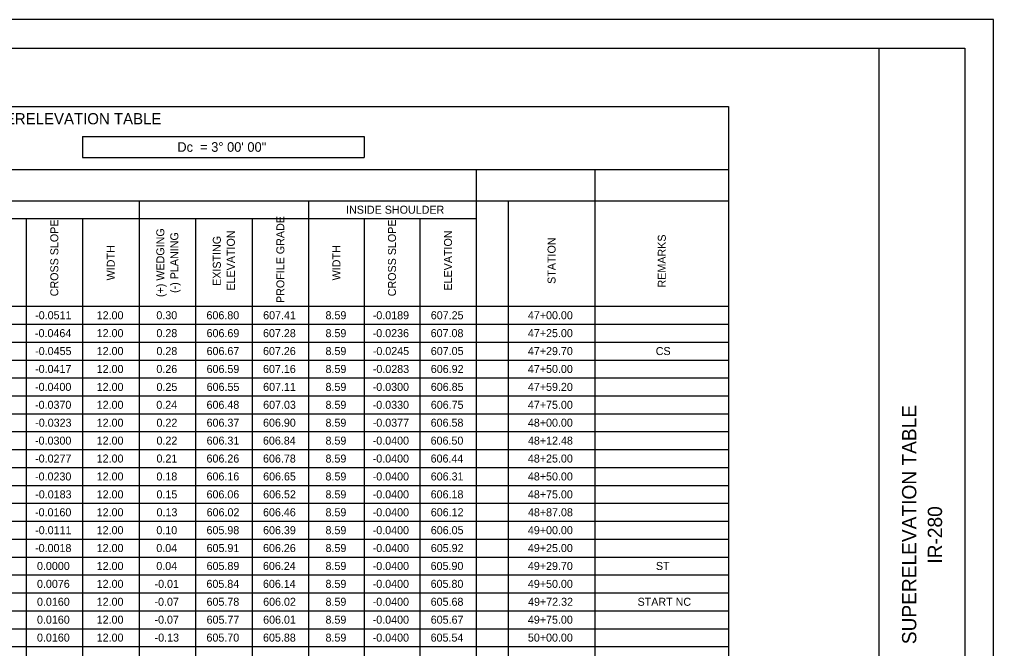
# Model space of a CAD drawing. Extents: x 0 to 34, y 0 to 22.
# Drawn here: x 16.97 to 34, y 11.01 to 22 of the extents above; entities that cross this region are included whole.
import ezdxf

# ---------------------------------------------------------------- set-up
doc = ezdxf.new("R2010")
doc.units = 0
for name, color, linetype in [('Default', 7, 'Continuous'), ('SH_Border', 7, 'Continuous'), ('SH_Cut_Line', 7, 'Continuous'), ('SH_Data', 7, 'Continuous')]:
    doc.layers.add(name, color=color, linetype=linetype)

msp = doc.modelspace()

# ---------------------------------------------------------------- linework, layer by layer
at = {"layer": 'Default'}
for p, q in [((4.135, 20.48), (29.368, 20.48)), ((29.368, 20.48), (29.368, 1.522)), ((18.069, 19.953), (22.994, 19.953)), ((18.069, 19.953), (18.069, 19.591)), ((22.994, 19.953), (22.994, 19.591)), ((18.069, 19.591), (22.994, 19.591)), ((4.135, 19.376), (29.368, 19.376)), ((24.954, 19.376), (24.954, 1.522)), ((27.029, 19.376), (27.029, 1.522)), ((4.135, 18.833), (29.368, 18.833)), ((19.057, 18.833), (19.057, 1.522)), ((22.022, 18.833), (22.022, 1.522)), ((25.514, 18.833), (25.514, 1.522)), ((4.135, 18.52), (24.954, 18.52)), ((17.081, 18.52), (17.081, 1.522)), ((18.069, 18.52), (18.069, 1.522)), ((20.046, 18.52), (20.046, 1.522)), ((21.034, 18.52), (21.034, 1.522)), ((22.994, 18.52), (22.994, 1.522)), ((23.966, 18.52), (23.966, 1.522)), ((4.135, 16.988), (29.368, 16.988)), ((4.135, 16.675), (29.368, 16.675)), ((4.135, 16.362), (29.368, 16.362)), ((4.135, 16.049), (29.368, 16.049)), ((4.135, 15.736), (29.368, 15.736)), ((4.135, 15.424), (29.368, 15.424)), ((4.135, 15.111), (29.368, 15.111)), ((4.135, 14.798), (29.368, 14.798)), ((4.135, 14.485), (29.368, 14.485)), ((4.135, 14.172), (29.368, 14.172)), ((4.135, 13.859), (29.368, 13.859)), ((4.135, 13.546), (29.368, 13.546)), ((4.135, 13.233), (29.368, 13.233)), ((4.135, 12.92), (29.368, 12.92)), ((4.135, 12.607), (29.368, 12.607)), ((4.135, 12.294), (29.368, 12.294)), ((4.135, 11.981), (29.368, 11.981)), ((4.135, 11.668), (29.368, 11.668)), ((4.135, 11.355), (29.368, 11.355)), ((4.135, 11.042), (29.368, 11.042))]:
    msp.add_line(p, q, dxfattribs=at)
at = {"layer": 'SH_Border'}
msp.add_line((32, 0.5), (32, 21.5), dxfattribs=at)
msp.add_lwpolyline([(1.5, 21.5), (33.5, 21.5), (33.5, 0.5), (1.5, 0.5)], close=True, dxfattribs=at)
at = {"layer": 'SH_Cut_Line'}
msp.add_lwpolyline([(0, 0), (34, 0), (34, 22), (0, 22)], close=True, dxfattribs=at)

# ---------------------------------------------------------------- texts
at = {"layer": 'Default'}
for s, height, p in [('WOO/LUC-280-06.20/00.00 - SUPERELEVATION TABLE', 0.196, (12.689, 20.168)), ('Dc  = 3° 00\' 00"', 0.168, (19.726, 19.688)), ('INSIDE SHOULDER', 0.14, (22.678, 18.606)), ('-0.0511', 0.14, (17.24, 16.762)), ('12.00', 0.14, (18.316, 16.762)), ('0.30', 0.14, (19.36, 16.762)), ('606.80', 0.14, (20.236, 16.762)), ('607.41', 0.14, (21.227, 16.762)), ('8.59', 0.14, (22.318, 16.762)), ('-0.0189', 0.14, (23.144, 16.762)), ('607.25', 0.14, (24.159, 16.762)), ('47+00.00', 0.14, (25.857, 16.762)), ('-0.0464', 0.14, (17.237, 16.449)), ('12.00', 0.14, (18.316, 16.449)), ('0.28', 0.14, (19.361, 16.449)), ('606.69', 0.14, (20.238, 16.449)), ('607.28', 0.14, (21.225, 16.449)), ('8.59', 0.14, (22.318, 16.449)), ('-0.0236', 0.14, (23.143, 16.449)), ('607.08', 0.14, (24.157, 16.449)), ('47+25.00', 0.14, (25.857, 16.449)), ('-0.0455', 0.14, (17.24, 16.136)), ('12.00', 0.14, (18.316, 16.136)), ('0.28', 0.14, (19.361, 16.136)), ('606.67', 0.14, (20.238, 16.136)), ('607.26', 0.14, (21.225, 16.136)), ('8.59', 0.14, (22.318, 16.136)), ('-0.0245', 0.14, (23.145, 16.136)), ('607.05', 0.14, (24.159, 16.136)), ('47+29.70', 0.14, (25.857, 16.136)), ('CS', 0.14, (28.093, 16.136)), ('-0.0417', 0.14, (17.239, 15.823)), ('12.00', 0.14, (18.316, 15.823)), ('0.26', 0.14, (19.36, 15.823)), ('606.59', 0.14, (20.238, 15.823)), ('607.16', 0.14, (21.225, 15.823)), ('8.59', 0.14, (22.318, 15.823)), ('-0.0283', 0.14, (23.145, 15.823)), ('606.92', 0.14, (24.159, 15.823)), ('47+50.00', 0.14, (25.857, 15.823)), ('-0.0400', 0.14, (17.238, 15.51)), ('12.00', 0.14, (18.316, 15.51)), ('0.25', 0.14, (19.362, 15.51)), ('606.55', 0.14, (20.239, 15.51)), ('607.11', 0.14, (21.227, 15.51)), ('8.59', 0.14, (22.318, 15.51)), ('-0.0300', 0.14, (23.143, 15.51)), ('606.85', 0.14, (24.159, 15.51)), ('47+59.20', 0.14, (25.857, 15.51)), ('-0.0370', 0.14, (17.238, 15.197)), ('12.00', 0.14, (18.316, 15.197)), ('0.24', 0.14, (19.359, 15.197)), ('606.48', 0.14, (20.237, 15.197)), ('607.03', 0.14, (21.227, 15.197)), ('8.59', 0.14, (22.318, 15.197)), ('-0.0330', 0.14, (23.143, 15.197)), ('606.75', 0.14, (24.159, 15.197)), ('47+75.00', 0.14, (25.857, 15.197)), ('-0.0323', 0.14, (17.241, 14.884)), ('12.00', 0.14, (18.316, 14.884)), ('0.22', 0.14, (19.362, 14.884)), ('606.37', 0.14, (20.238, 14.884)), ('606.90', 0.14, (21.225, 14.884)), ('8.59', 0.14, (22.318, 14.884)), ('-0.0377', 0.14, (23.144, 14.884)), ('606.58', 0.14, (24.157, 14.884)), ('48+00.00', 0.14, (25.857, 14.884)), ('-0.0300', 0.14, (17.238, 14.571)), ('12.00', 0.14, (18.316, 14.571)), ('0.22', 0.14, (19.362, 14.571)), ('606.31', 0.14, (20.238, 14.571)), ('606.84', 0.14, (21.224, 14.571)), ('8.59', 0.14, (22.318, 14.571)), ('-0.0400', 0.14, (23.143, 14.571)), ('606.50', 0.14, (24.156, 14.571)), ('48+12.48', 0.14, (25.858, 14.571)), ('-0.0277', 0.14, (17.239, 14.258)), ('12.00', 0.14, (18.316, 14.258)), ('0.21', 0.14, (19.362, 14.258)), ('606.26', 0.14, (20.237, 14.258)), ('606.78', 0.14, (21.225, 14.258)), ('8.59', 0.14, (22.318, 14.258)), ('-0.0400', 0.14, (23.143, 14.258)), ('606.44', 0.14, (24.156, 14.258)), ('48+25.00', 0.14, (25.857, 14.258)), ('-0.0230', 0.14, (17.238, 13.945)), ('12.00', 0.14, (18.316, 13.945)), ('0.18', 0.14, (19.361, 13.945)), ('606.16', 0.14, (20.237, 13.945)), ('606.65', 0.14, (21.227, 13.945)), ('8.59', 0.14, (22.318, 13.945)), ('-0.0400', 0.14, (23.143, 13.945)), ('606.31', 0.14, (24.158, 13.945)), ('48+50.00', 0.14, (25.857, 13.945)), ('-0.0183', 0.14, (17.241, 13.632)), ('12.00', 0.14, (18.316, 13.632)), ('0.15', 0.14, (19.362, 13.632)), ('606.06', 0.14, (20.237, 13.632)), ('606.52', 0.14, (21.227, 13.632)), ('8.59', 0.14, (22.318, 13.632)), ('-0.0400', 0.14, (23.143, 13.632)), ('606.18', 0.14, (24.157, 13.632)), ('48+75.00', 0.14, (25.857, 13.632)), ('-0.0160', 0.14, (17.238, 13.319)), ('12.00', 0.14, (18.316, 13.319)), ('0.13', 0.14, (19.363, 13.319)), ('606.02', 0.14, (20.239, 13.319)), ('606.46', 0.14, (21.225, 13.319)), ('8.59', 0.14, (22.318, 13.319)), ('-0.0400', 0.14, (23.143, 13.319)), ('606.12', 0.14, (24.159, 13.319)), ('48+87.08', 0.14, (25.858, 13.319)), ('-0.0111', 0.14, (17.24, 13.006)), ('12.00', 0.14, (18.316, 13.006)), ('0.10', 0.14, (19.36, 13.006)), ('605.98', 0.14, (20.237, 13.006)), ('606.39', 0.14, (21.226, 13.006)), ('8.59', 0.14, (22.318, 13.006)), ('-0.0400', 0.14, (23.143, 13.006)), ('606.05', 0.14, (24.159, 13.006)), ('49+00.00', 0.14, (25.857, 13.006)), ('-0.0018', 0.14, (17.239, 12.694)), ('12.00', 0.14, (18.316, 12.694)), ('0.04', 0.14, (19.359, 12.694)), ('605.91', 0.14, (20.238, 12.694)), ('606.26', 0.14, (21.225, 12.694)), ('8.59', 0.14, (22.318, 12.694)), ('-0.0400', 0.14, (23.143, 12.694)), ('605.92', 0.14, (24.159, 12.694)), ('49+25.00', 0.14, (25.857, 12.694)), ('0.0000', 0.14, (17.272, 12.381)), ('12.00', 0.14, (18.316, 12.381)), ('0.04', 0.14, (19.359, 12.381)), ('605.89', 0.14, (20.238, 12.381)), ('606.24', 0.14, (21.224, 12.381)), ('8.59', 0.14, (22.318, 12.381)), ('-0.0400', 0.14, (23.143, 12.381)), ('605.90', 0.14, (24.156, 12.381)), ('49+29.70', 0.14, (25.857, 12.381)), ('ST', 0.14, (28.096, 12.381)), ('0.0076', 0.14, (17.272, 12.068)), ('12.00', 0.14, (18.316, 12.068)), ('-0.01', 0.14, (19.328, 12.068)), ('605.84', 0.14, (20.236, 12.068)), ('606.14', 0.14, (21.224, 12.068)), ('8.59', 0.14, (22.318, 12.068)), ('-0.0400', 0.14, (23.143, 12.068)), ('605.80', 0.14, (24.156, 12.068)), ('49+50.00', 0.14, (25.857, 12.068)), ('0.0160', 0.14, (17.272, 11.755)), ('12.00', 0.14, (18.316, 11.755)), ('-0.07', 0.14, (19.327, 11.755)), ('605.78', 0.14, (20.237, 11.755)), ('606.02', 0.14, (21.227, 11.755)), ('8.59', 0.14, (22.318, 11.755)), ('-0.0400', 0.14, (23.143, 11.755)), ('605.68', 0.14, (24.157, 11.755)), ('49+72.32', 0.14, (25.86, 11.755)), ('START NC', 0.14, (27.775, 11.755)), ('0.0160', 0.14, (17.272, 11.442)), ('12.00', 0.14, (18.316, 11.442)), ('-0.07', 0.14, (19.327, 11.442)), ('605.77', 0.14, (20.238, 11.442)), ('606.01', 0.14, (21.227, 11.442)), ('8.59', 0.14, (22.318, 11.442)), ('-0.0400', 0.14, (23.143, 11.442)), ('605.67', 0.14, (24.158, 11.442)), ('49+75.00', 0.14, (25.857, 11.442)), ('0.0160', 0.14, (17.272, 11.129)), ('12.00', 0.14, (18.316, 11.129)), ('-0.13', 0.14, (19.329, 11.129)), ('605.70', 0.14, (20.236, 11.129)), ('605.88', 0.14, (21.225, 11.129)), ('8.59', 0.14, (22.318, 11.129)), ('-0.0400', 0.14, (23.143, 11.129)), ('605.54', 0.14, (24.156, 11.129)), ('50+00.00', 0.14, (25.857, 11.129))]:
    msp.add_text(s, height=height, dxfattribs=at).set_placement(p)
for s, p in [('CROSS SLOPE', (17.645, 17.163)), ('PROFILE GRADE', (21.598, 17.046)), ('CROSS SLOPE', (23.55, 17.163)), ('(+) WEDGING', (19.499, 17.15)), ('(-) PLANING', (19.744, 17.222)), ('ELEVATION', (20.732, 17.263)), ('ELEVATION', (24.53, 17.263)), ('REMARKS', (28.269, 17.317)), ('EXISTING ', (20.487, 17.345)), ('STATION', (26.341, 17.38)), ('WIDTH', (18.633, 17.441)), ('WIDTH', (22.578, 17.441))]:
    msp.add_text(s, height=0.14, rotation=90, dxfattribs=at).set_placement(p)
at = {"layer": 'SH_Data'}
for s, p in [('SUPERELEVATION TABLE', (32.65, 11.084)), ('IR-280', (33.1, 12.491))]:
    msp.add_text(s, height=0.25, rotation=90, dxfattribs=at).set_placement(p)

doc.saveas('drawing.dxf')
